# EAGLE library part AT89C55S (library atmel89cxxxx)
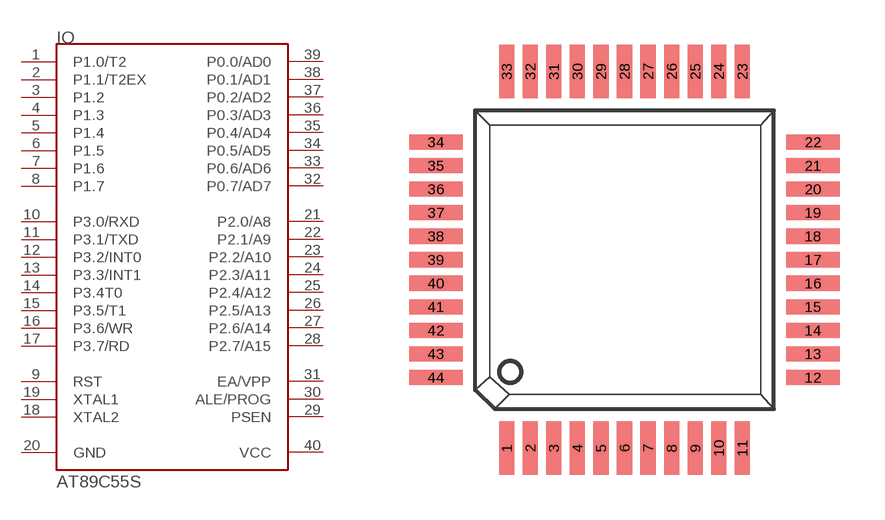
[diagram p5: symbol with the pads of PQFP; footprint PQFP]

Designator prefix IO

## AT89C55S  [PQFP]
1  P1.0/T2
2  P1.1/T2EX
3  P1.2
4  P1.3
5  P1.4
6  P1.5
7  P1.6
8  P1.7
9  RST
10  P3.0/RXD
11  P3.1/TXD
12  P3.2/INT0
13  P3.3/INT1
14  P3.4T0
15  P3.5/T1
16  P3.6/WR
17  P3.7/RD
18  XTAL2
19  XTAL1
20  GND  pwr
21  P2.0/A8
22  P2.1/A9
23  P2.2/A10
24  P2.3/A11
25  P2.4/A12
26  P2.5/A13
27  P2.6/A14
28  P2.7/A15
29  PSEN
30  ALE/PROG
31  EA/VPP
32  P0.7/AD7
33  P0.6/AD6
34  P0.5/AD5
35  P0.4/AD4
36  P0.3/AD3
37  P0.2/AD2
38  P0.1/AD1
39  P0.0/AD0
40  VCC  pwr

## Footprint PQFP (pad centres in mm)
smd 0.508 x 1.778: 1 -4.217,-7.289; 2 -3.43,-7.289; 3 -2.642,-7.289; 4 -1.855,-7.289; 5 -1.067,-7.289; 6 -0.28,-7.289; 7 0.507,-7.289; 8 1.295,-7.289; 9 2.082,-7.289; 10 2.87,-7.289; 11 3.657,-7.289; 23 3.657,5.309; 24 2.87,5.309; 25 2.082,5.309; 26 1.295,5.309; 27 0.507,5.309; 28 -0.28,5.309; 29 -1.067,5.309; 30 -1.855,5.309; 31 -2.642,5.309; 32 -3.43,5.309; 33 -4.217,5.309
smd 1.778 x 0.508: 12 6.019,-4.927; 13 6.019,-4.14; 14 6.019,-3.352; 15 6.019,-2.565; 16 6.019,-1.777; 17 6.019,-0.99; 18 6.019,-0.203; 19 6.019,0.585; 20 6.019,1.372; 21 6.019,2.16; 22 6.019,2.947; 34 -6.579,2.947; 35 -6.579,2.16; 36 -6.579,1.372; 37 -6.579,0.585; 38 -6.579,-0.203; 39 -6.579,-0.99; 40 -6.579,-1.777; 41 -6.579,-2.565; 42 -6.579,-3.352; 43 -6.579,-4.14; 44 -6.579,-4.927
